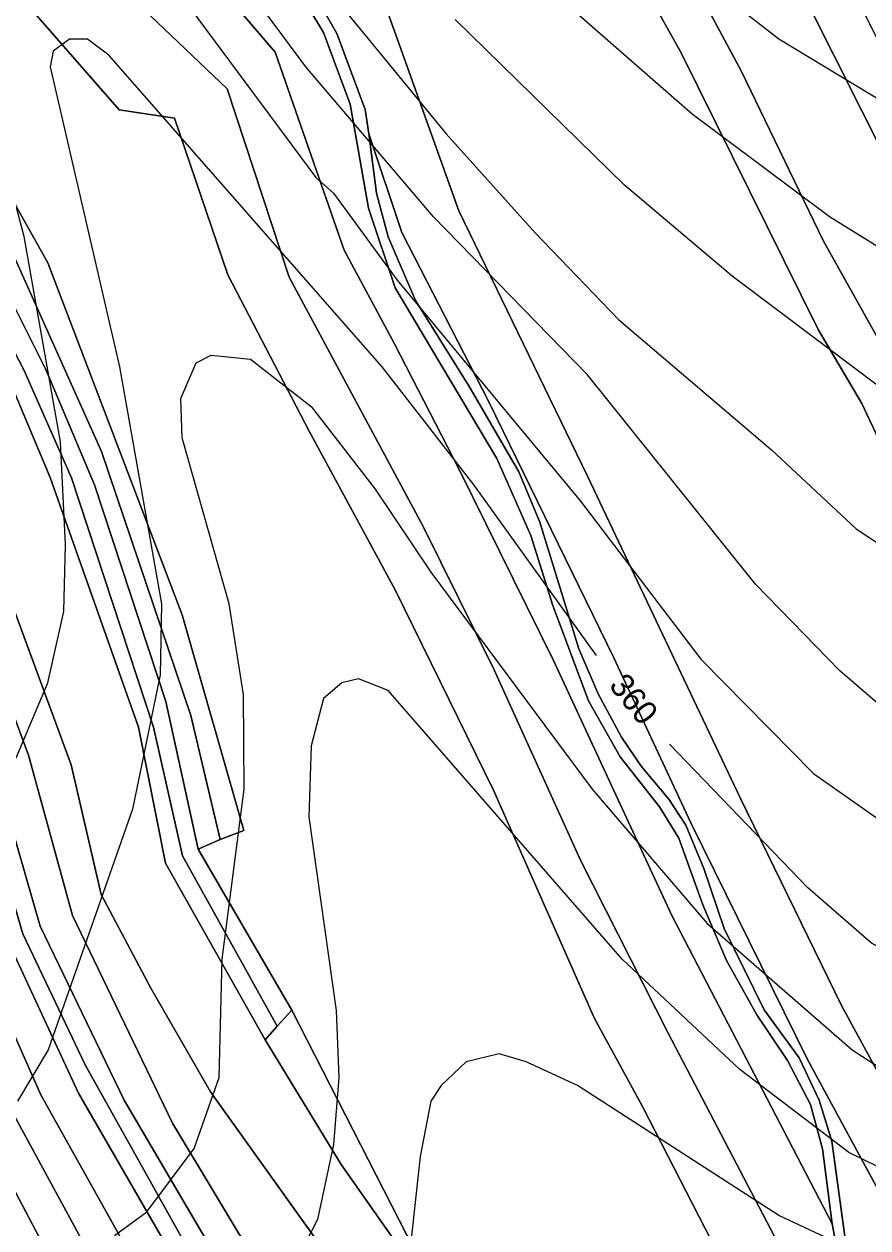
# Model space of a CAD drawing. Extents: x -510989 to -501240, y -1184665 to -1176089.
# Drawn here: x -503788.9 to -503575, y -1184005.1 to -1183700.2 of the extents above; entities that cross this region are included whole.
import ezdxf

# ---------------------------------------------------------------- set-up
doc = ezdxf.new("R2010")
doc.units = 0
for name, color, linetype in [('lesni_pozemek', 7, 'Continuous'), ('ostatni_plocha_x_ostatni_komunikace', 7, 'Continuous'), ('STAV_zaplavove_uzemi', 7, 'Continuous'), ('vrstevnice_01', 7, 'Continuous'), ('vrstevnice_02', 7, 'Continuous'), ('vrstevnice_04', 7, 'Continuous')]:
    doc.layers.add(name, color=color, linetype=linetype)

msp = doc.modelspace()

# ---------------------------------------------------------------- linework, layer by layer
at = {"layer": 'lesni_pozemek'}
for points in [[(-503728.62, -1183471.74), (-503691.85, -1183518.28), (-503657.3, -1183563.82), (-503630.7, -1183603.31), (-503587.48, -1183674.13), (-503559.07, -1183730.95), (-503535.3, -1183775.28), (-503494.59, -1183857.89), (-503467.6, -1183908.87), (-503444.44, -1183950.57), (-503452.2, -1183962.13), (-503472.04, -1183928.43), (-503489.75, -1183894.93), (-503504.72, -1183863.49), (-503545.08, -1183781.53), (-503569.52, -1183736.09), (-503597.66, -1183680.08), (-503640.08, -1183608.41), (-503666.58, -1183570.25), (-503702.2, -1183523.58), (-503704.29, -1183514.52), (-503710.83, -1183503.88), (-503732.92, -1183473.63), (-503757.64, -1183437.65)], [(-503702.34, -1183529.64), (-503702.2, -1183523.58), (-503666.58, -1183570.25), (-503640.08, -1183608.41), (-503597.66, -1183680.08), (-503569.52, -1183736.09), (-503545.08, -1183781.53), (-503504.72, -1183863.49), (-503489.75, -1183894.93), (-503472.04, -1183928.43), (-503452.2, -1183962.13), (-503464.49, -1183989.9), (-503471.18, -1183974.63), (-503503.05, -1183923.12), (-503533.25, -1183859.97), (-503566.41, -1183790.65), (-503586.33, -1183754.98), (-503607.08, -1183711.98), (-503630.64, -1183668.25), (-503652.21, -1183630.71), (-503678.37, -1183593.17), (-503718.7, -1183539.6), (-503708.68, -1183537.99), (-503704.44, -1183534.65)], [(-503723.14, -1183541.1), (-503718.7, -1183539.6), (-503678.37, -1183593.17), (-503652.21, -1183630.71), (-503630.64, -1183668.25), (-503607.08, -1183711.98), (-503586.33, -1183754.98), (-503566.41, -1183790.65), (-503533.25, -1183859.97), (-503503.05, -1183923.12), (-503471.18, -1183974.63), (-503464.49, -1183989.9), (-503470.2, -1184003.02), (-503478.74, -1183984.9), (-503487.73, -1183968.99), (-503513.65, -1183929.65), (-503543.5, -1183866.33), (-503576.52, -1183796.27), (-503587.58, -1183777.55), (-503622.31, -1183707.4), (-503662.92, -1183634.99), (-503689.76, -1183596.42), (-503727.89, -1183546.54)], [(-503973.7, -1183580.21), (-503967.42, -1183575.47), (-503953.32, -1183592.85), (-503940.15, -1183610.84), (-503925.17, -1183637.07), (-503875, -1183734.39), (-503853.34, -1183771.91), (-503838.27, -1183795.1), (-503823.83, -1183814.7), (-503794.54, -1183894.91), (-503784.87, -1183928.69), (-503763.52, -1183972.72), (-503707.12, -1184068.85), (-503713.72, -1184066.97), (-503735.95, -1184030.77), (-503773.46, -1183963.81), (-503789.2, -1183930.62), (-503800.23, -1183893.46), (-503821.51, -1183835.13), (-503830.08, -1183814.58), (-503857.78, -1183773.87), (-503877.64, -1183741.34), (-503929.28, -1183640.96)], [(-503923.76, -1183607.91), (-503941.52, -1183574.63), (-503907.86, -1183618.07), (-503877.34, -1183671.41), (-503857.25, -1183720.73), (-503808.09, -1183803.62), (-503776.93, -1183887.81), (-503769.34, -1183920.65), (-503756.77, -1183944.36), (-503741.61, -1183970.6), (-503712.6, -1184011.28), (-503680.96, -1184060.99), (-503667.47, -1184079.1), (-503694.94, -1184072.32), (-503751.3, -1183978.62), (-503776.6, -1183926), (-503787.83, -1183885.37), (-503816.55, -1183807.93), (-503850.68, -1183754.94), (-503867.66, -1183724.35), (-503888.17, -1183679.49), (-503918.27, -1183624.04), (-503926.42, -1183608.7)], [(-503932.58, -1183610.17), (-503926.42, -1183608.7), (-503918.27, -1183624.04), (-503888.17, -1183679.49), (-503867.66, -1183724.35), (-503850.68, -1183754.94), (-503816.55, -1183807.93), (-503787.83, -1183885.37), (-503776.6, -1183926), (-503751.3, -1183978.62), (-503694.94, -1184072.32), (-503707.12, -1184068.85), (-503763.52, -1183972.72), (-503784.87, -1183928.69), (-503794.54, -1183894.91), (-503823.83, -1183814.7), (-503838.27, -1183795.1), (-503853.34, -1183771.91), (-503875, -1183734.39), (-503925.17, -1183637.07), (-503940.15, -1183610.84)], [(-503900.05, -1183728.04), (-503892.22, -1183725.13), (-503880.05, -1183748.32), (-503866.2, -1183771.19), (-503833.89, -1183817.35), (-503804.04, -1183897.35), (-503791.87, -1183934.91), (-503775.13, -1183970.96), (-503720.64, -1184065.31), (-503730.86, -1184063.76), (-503751.05, -1184031.5), (-503784.63, -1183971.4), (-503801.21, -1183934.2), (-503812.45, -1183899.3), (-503831.14, -1183853.16), (-503842.23, -1183821.92), (-503877.86, -1183773.44), (-503893.19, -1183746.72), (-503904.72, -1183729.79)], [(-503904.72, -1183729.79), (-503893.19, -1183746.72), (-503877.86, -1183773.44), (-503842.23, -1183821.92), (-503831.14, -1183853.16), (-503812.45, -1183899.3), (-503801.21, -1183934.2), (-503784.63, -1183971.4), (-503751.05, -1184031.5), (-503730.86, -1184063.76), (-503741.77, -1184062.1), (-503759.53, -1184035.2), (-503797.58, -1183965.4), (-503808.59, -1183940.4), (-503820.43, -1183905.78), (-503841.38, -1183855.53), (-503850.64, -1183826.99), (-503885.26, -1183783.71), (-503890.42, -1183769.29), (-503901.81, -1183755.02), (-503908.95, -1183736.5)], [(-503889.81, -1183794.49), (-503885.26, -1183783.71), (-503850.64, -1183826.99), (-503841.38, -1183855.53), (-503820.43, -1183905.78), (-503808.59, -1183940.4), (-503797.58, -1183965.4), (-503759.53, -1184035.2), (-503741.77, -1184062.1), (-503754.12, -1184060.23), (-503768.09, -1184039.72), (-503805.46, -1183968.92), (-503816.03, -1183944.5), (-503829.24, -1183908.06), (-503850.19, -1183858.72), (-503859.75, -1183830.63)], [(-503895.32, -1183800.87), (-503889.81, -1183794.49), (-503859.75, -1183830.63), (-503850.19, -1183858.72), (-503829.24, -1183908.06), (-503816.03, -1183944.5), (-503805.46, -1183968.92), (-503768.09, -1184039.72), (-503754.12, -1184060.23), (-503767.28, -1184058.24), (-503778.46, -1184038.52), (-503810.59, -1183978.68), (-503824.96, -1183943.91), (-503860.61, -1183859.76), (-503868.2, -1183834.35)], [(-503724.76, -1183954.02), (-503721.05, -1183949.98), (-503691.91, -1184006.91), (-503654.54, -1184059.93), (-503635.2, -1184080.62), (-503637.88, -1184082.63), (-503657.74, -1184061.34), (-503708.48, -1183989.05), (-503727.82, -1183957.43)]]:
    msp.add_lwpolyline(points, close=True, dxfattribs=at)
for points in [[(-503662.92, -1183634.99), (-503622.31, -1183707.4), (-503587.58, -1183777.55), (-503576.52, -1183796.27), (-503543.5, -1183866.33), (-503513.65, -1183929.65), (-503487.73, -1183968.99), (-503478.74, -1183984.9), (-503470.2, -1184003.02), (-503477.05, -1184015.77), (-503492.95, -1184041.99), (-503503.44, -1184052.15), (-503519.21, -1184065.24), (-503532.36, -1184039.22), (-503581.63, -1183948.77), (-503607.29, -1183896.32), (-503646.1, -1183814.64), (-503678.66, -1183747.47), (-503699.47, -1183689.36)], [(-503929.28, -1183640.96), (-503877.64, -1183741.34), (-503857.78, -1183773.87), (-503830.08, -1183814.58), (-503821.51, -1183835.13), (-503800.23, -1183893.46), (-503789.2, -1183930.62), (-503773.46, -1183963.81), (-503735.95, -1184030.77), (-503713.72, -1184066.97), (-503718.36, -1184065.65), (-503720.64, -1184065.31), (-503775.13, -1183970.96), (-503791.87, -1183934.91), (-503804.04, -1183897.35), (-503833.89, -1183817.35), (-503866.2, -1183771.19), (-503880.05, -1183748.32), (-503892.22, -1183725.13), (-503903.02, -1183704.47), (-503915.09, -1183676.77)], [(-503846.64, -1183645.9), (-503830.48, -1183701.14), (-503808.25, -1183738.14), (-503783.4, -1183787.65), (-503771.07, -1183816.84), (-503753, -1183871.73), (-503744.79, -1183909.13), (-503721.05, -1183949.98), (-503724.76, -1183954.02), (-503748.71, -1183910.82), (-503756.11, -1183878.29), (-503776.89, -1183815.13), (-503788.99, -1183787.77), (-503810.24, -1183746.79), (-503834.07, -1183708.75), (-503851.8, -1183649.23)], [(-503824.66, -1183699.4), (-503800.08, -1183740), (-503769.25, -1183808.46), (-503746.65, -1183875.28), (-503739.21, -1183906.7), (-503744.79, -1183909.13), (-503753, -1183871.73), (-503771.07, -1183816.84), (-503783.4, -1183787.65), (-503808.25, -1183738.14), (-503830.48, -1183701.14), (-503846.64, -1183645.9)], [(-503851.8, -1183649.23), (-503834.07, -1183708.75), (-503810.24, -1183746.79), (-503788.99, -1183787.77), (-503776.89, -1183815.13), (-503756.11, -1183878.29), (-503748.71, -1183910.82), (-503724.76, -1183954.02), (-503727.82, -1183957.43), (-503753.06, -1183912.7), (-503759.87, -1183878.29), (-503782.29, -1183815.01), (-503791.33, -1183793.52), (-503809.77, -1183760.41), (-503823.51, -1183736.34), (-503839.1, -1183710.79), (-503858.14, -1183652.63)], [(-503858.14, -1183652.63), (-503839.1, -1183710.79), (-503823.51, -1183736.34), (-503809.77, -1183760.41), (-503791.33, -1183793.52), (-503782.29, -1183815.01), (-503759.87, -1183878.29), (-503753.06, -1183912.7), (-503727.82, -1183957.43), (-503708.48, -1183989.05), (-503657.74, -1184061.34), (-503637.88, -1184082.63), (-503639.64, -1184083.95), (-503644.69, -1184084.68), (-503667.47, -1184079.1), (-503680.96, -1184060.99), (-503712.6, -1184011.28), (-503741.61, -1183970.6), (-503756.77, -1183944.36), (-503769.34, -1183920.65), (-503776.93, -1183887.81), (-503808.09, -1183803.62), (-503857.25, -1183720.73), (-503877.34, -1183671.41)], [(-503699.47, -1183689.36), (-503678.66, -1183747.47), (-503646.1, -1183814.64), (-503607.29, -1183896.32), (-503581.63, -1183948.77), (-503532.36, -1184039.22), (-503519.21, -1184065.24), (-503531.57, -1184073.22), (-503552.36, -1184032.36), (-503590.26, -1183962.48), (-503619.87, -1183902.47), (-503639.35, -1183860.67), (-503671.07, -1183795.86), (-503693.13, -1183752.97), (-503701.5, -1183727.98), (-503702.43, -1183721.81), (-503709.64, -1183702.51), (-503720.81, -1183682.97)], [(-503770.96, -1183684.53), (-503737.4, -1183716.6), (-503721.68, -1183764.28), (-503687.75, -1183827.43), (-503669.79, -1183863.59), (-503647.74, -1183912.1), (-503625.59, -1183955.76), (-503578.51, -1184045.73), (-503590.64, -1184055.04), (-503632.12, -1183974.33), (-503644.33, -1183952.06), (-503669.88, -1183894.19), (-503694.71, -1183843.63), (-503716.62, -1183803.28), (-503737.24, -1183763.67), (-503750.79, -1183723.99), (-503764.78, -1183721.86), (-503787.11, -1183696.42)], [(-503744.59, -1183684.65), (-503725.26, -1183707.27), (-503707.77, -1183757.47), (-503695.01, -1183781.13), (-503678.56, -1183813.02), (-503654.69, -1183861.36), (-503624.66, -1183925.96), (-503584.07, -1184004.05), (-503579.34, -1184029.04), (-503578.51, -1184045.73), (-503625.59, -1183955.76), (-503647.74, -1183912.1), (-503669.79, -1183863.59), (-503687.75, -1183827.43), (-503721.68, -1183764.28), (-503737.4, -1183716.6), (-503770.96, -1183684.53)], [(-503718.95, -1183692.39), (-503713.01, -1183702.28), (-503706.27, -1183720.42), (-503701.62, -1183746.82), (-503694.87, -1183766.93), (-503669.06, -1183810.19), (-503660.45, -1183829.73), (-503654.87, -1183847.4), (-503645.8, -1183871.59), (-503637.78, -1183885.78), (-503627.78, -1183898.46), (-503622.89, -1183906.36), (-503616.86, -1183923.28), (-503610.8, -1183937.39), (-503603.17, -1183951.17), (-503595.36, -1183962.71), (-503589.55, -1183973.83), (-503586.48, -1183985.04), (-503584.07, -1184004.05), (-503624.66, -1183925.96), (-503654.69, -1183861.36), (-503678.56, -1183813.02), (-503695.01, -1183781.13), (-503707.77, -1183757.47), (-503725.26, -1183707.27), (-503744.59, -1183684.65)], [(-503819.92, -1183697.23), (-503794.33, -1183740.3), (-503782.85, -1183760.63), (-503748.83, -1183849.84), (-503733.2, -1183904.47), (-503739.21, -1183906.7), (-503746.65, -1183875.28), (-503769.25, -1183808.46), (-503800.08, -1183740), (-503824.66, -1183699.4)], [(-503787.11, -1183696.42), (-503764.78, -1183721.86), (-503750.79, -1183723.99), (-503737.24, -1183763.67), (-503716.62, -1183803.28), (-503694.71, -1183843.63), (-503669.88, -1183894.19), (-503644.33, -1183952.06), (-503632.12, -1183974.33), (-503590.64, -1184055.04)], [(-503580.18, -1184012.21), (-503584.13, -1183983.14), (-503587.3, -1183972.77), (-503592.44, -1183962.03), (-503601.25, -1183949.9), (-503611.41, -1183929.26), (-503616.57, -1183914.09), (-503621.15, -1183903.11), (-503625.45, -1183896.48), (-503632.43, -1183888.11), (-503637.43, -1183880.78), (-503643.36, -1183869.85), (-503648.24, -1183858.45), (-503658.13, -1183826.36), (-503663.48, -1183813.56), (-503676.15, -1183791.82), (-503689.64, -1183770.19), (-503696.62, -1183754.03), (-503699.53, -1183742.98), (-503701.5, -1183727.98), (-503693.13, -1183752.97), (-503671.07, -1183795.86), (-503639.35, -1183860.67), (-503619.87, -1183902.47), (-503590.26, -1183962.48), (-503552.36, -1184032.36)], [(-503691.91, -1184006.91), (-503721.05, -1183949.98), (-503744.79, -1183909.13), (-503739.21, -1183906.7), (-503733.2, -1183904.47), (-503748.83, -1183849.84), (-503782.85, -1183760.63), (-503794.33, -1183740.3)]]:
    msp.add_lwpolyline(points, dxfattribs=at)
at = {"layer": 'ostatni_plocha_x_ostatni_komunikace'}
for points in [[(-503720.81, -1183682.97), (-503709.64, -1183702.51), (-503702.43, -1183721.81), (-503701.5, -1183727.98), (-503699.53, -1183742.98), (-503696.62, -1183754.03), (-503689.64, -1183770.19), (-503676.15, -1183791.82), (-503663.48, -1183813.56), (-503658.13, -1183826.36), (-503648.24, -1183858.45), (-503643.36, -1183869.85), (-503637.43, -1183880.78), (-503632.43, -1183888.11), (-503625.45, -1183896.48), (-503621.15, -1183903.11), (-503616.57, -1183914.09), (-503611.41, -1183929.26), (-503601.25, -1183949.9), (-503592.44, -1183962.03), (-503587.3, -1183972.77), (-503584.13, -1183983.14), (-503580.18, -1184012.21)], [(-503579.34, -1184029.04), (-503584.07, -1184004.05), (-503586.48, -1183985.04), (-503589.55, -1183973.83), (-503595.36, -1183962.71), (-503603.17, -1183951.17), (-503610.8, -1183937.39), (-503616.86, -1183923.28), (-503622.89, -1183906.36), (-503627.78, -1183898.46), (-503637.78, -1183885.78), (-503645.8, -1183871.59), (-503654.87, -1183847.4), (-503660.45, -1183829.73), (-503669.06, -1183810.19), (-503694.87, -1183766.93), (-503701.62, -1183746.82), (-503706.27, -1183720.42), (-503713.01, -1183702.28), (-503718.95, -1183692.39)]]:
    msp.add_lwpolyline(points, dxfattribs=at)
at = {"layer": 'STAV_zaplavove_uzemi'}
msp.add_spline([(-502250.32, -1184002.61), (-502355.07, -1183875.41), (-502442.37, -1183790.61), (-502477.29, -1183700.82), (-502532.16, -1183578.61), (-502567.08, -1183448.91), (-502626.05, -1183402.34), (-502705.41, -1183380.59), (-502814.2, -1183349.87), (-502882.03, -1183297.39), (-502931.95, -1183237.24), (-503042.02, -1183107.97), (-503139.64, -1183018.94), (-503222.14, -1182957.59), (-503308.56, -1182839.96), (-503316.24, -1182784.92), (-503330.32, -1182756.77), (-503348.24, -1182719.65), (-503334.16, -1182651.82), (-503323.92, -1182595.5), (-503313.68, -1182526.39), (-503294.1, -1182480.5), (-503251.86, -1182396.03), (-503229.34, -1182314.37), (-503216.1, -1182227.15), (-503242.43, -1182174.5), (-503271.86, -1182129.59), (-503287.34, -1182081.58), (-503343.88, -1182028.1), (-503361.79, -1182008.91), (-503396.35, -1181952.59), (-503442.43, -1181933.39), (-503497.46, -1181888.6), (-503525.62, -1181860.44), (-503528.18, -1181837.4), (-503548.66, -1181767.01), (-503558.9, -1181729.89), (-503576.82, -1181682.53), (-503578.1, -1181621.1), (-503567.86, -1181572.46), (-503552.5, -1181536.63), (-503538.04, -1181458.36), (-503518.33, -1181411.9), (-503509.88, -1181341.51), (-503497.21, -1181207.63), (-503499.77, -1181097.56), (-503498.02, -1181031.35), (-503510.82, -1180970.85), (-503549.22, -1180952.23), (-503571.32, -1180940.6), (-503605.07, -1180937.11), (-503651.61, -1180939.44), (-503671.39, -1180917.33), (-503679.53, -1180892.89), (-503713.27, -1180871.95), (-503727.24, -1180859.15), (-503734.22, -1180833.55), (-503728.4, -1180799.81), (-503741.2, -1180770.72), (-503722.82, -1180725.17), (-503721.54, -1180703.41), (-503731.78, -1180697.01), (-503767.61, -1180699.57), (-503790.65, -1180697.01), (-503817.53, -1180697.01), (-503861.04, -1180686.77), (-503889.2, -1180675.25), (-503900.72, -1180668.85), (-503953.2, -1180679.09), (-503997.99, -1180697.01), (-504063.27, -1180722.61), (-504109.34, -1180749.49), (-504142.62, -1180776.36), (-504177.18, -1180796.84), (-504211.73, -1180817.32), (-504414.98, -1180961.5), (-504472.7, -1180998.11), (-504544.51, -1181068.5), (-504600.82, -1181143.12), (-504621.94, -1181196.62), (-504641.65, -1181267.01), (-504660.25, -1181350.62), (-504634.7, -1181398.32), (-504617.66, -1181447.72), (-504600.62, -1181492.01), (-504587, -1181548.23), (-504592.11, -1181628.29), (-504569.96, -1181682.81), (-504568.26, -1181664.07), (-504554.63, -1181621.48), (-504547.82, -1181597.63)], degree=3, dxfattribs=at)
at = {"layer": 'vrstevnice_01'}
for points in [[(-503392.59, -1183695), (-503413.81, -1183710), (-503445, -1183726), (-503474.31, -1183738), (-503497.69, -1183743), (-503524.19, -1183742), (-503547.81, -1183734), (-503597.59, -1183704), (-503628.31, -1183680)], [(-503318.3, -1183681.98), (-503390.91, -1183753), (-503439.59, -1183798), (-503454.19, -1183808), (-503464.69, -1183812), (-503485.31, -1183817), (-503501.59, -1183818), (-503515.19, -1183816), (-503542.31, -1183808), (-503566.81, -1183796), (-503609.41, -1183764), (-503636.69, -1183741), (-503679.59, -1183699)], [(-503325.32, -1183759.01), (-503354.31, -1183783), (-503373.41, -1183800), (-503374.19, -1183803), (-503380.09, -1183809), (-503400, -1183849), (-503402.69, -1183857), (-503406.59, -1183863), (-503419.41, -1183874), (-503430.59, -1183880), (-503457.59, -1183889), (-503490.91, -1183895), (-503519, -1183895), (-503536, -1183893), (-503548.81, -1183889), (-503565.81, -1183878), (-503582.09, -1183864), (-503603.5, -1183842), (-503646.09, -1183789), (-503685.09, -1183749), (-503717.5, -1183711), (-503736, -1183686)], [(-503643.79, -1183860.07), (-503674.81, -1183817), (-503698.09, -1183787), (-503767.41, -1183708), (-503772.81, -1183704), (-503777.41, -1183704), (-503781.5, -1183707), (-503782.31, -1183711), (-503764.69, -1183787), (-503754.09, -1183847), (-503754.41, -1183865), (-503761.41, -1183899), (-503782.81, -1183960), (-503790.59, -1183973)], [(-503332.43, -1183837.02), (-503343.59, -1183846), (-503352.09, -1183859), (-503358, -1183884), (-503362.09, -1183896), (-503372.19, -1183909), (-503383.31, -1183916), (-503438.09, -1183937), (-503481.91, -1183950), (-503500.41, -1183954), (-503515.81, -1183955), (-503539.5, -1183951), (-503548.31, -1183947), (-503574.09, -1183933), (-503590.19, -1183919), (-503625.28, -1183882.53)], [(-503365.81, -1183956), (-503479.69, -1183990), (-503512.19, -1183998), (-503527.41, -1184001), (-503543.69, -1184000), (-503561.5, -1183995), (-503579.81, -1183986), (-503607.41, -1183965), (-503637.31, -1183937), (-503696.59, -1183869), (-503704.09, -1183866), (-503708.31, -1183867), (-503713, -1183871), (-503716.09, -1183883), (-503716.69, -1183901), (-503709.81, -1183950), (-503709.09, -1183967), (-503710.5, -1183984), (-503714.5, -1184003), (-503720.69, -1184015)]]:
    msp.add_lwpolyline(points, dxfattribs=at)
at = {"layer": 'vrstevnice_02'}
for points in [[(-503758.69, -1183680), (-503714.91, -1183739), (-503710.5, -1183743), (-503694.31, -1183765), (-503647.81, -1183821), (-503617.31, -1183861), (-503588.81, -1183890), (-503566, -1183906), (-503540, -1183922), (-503527.09, -1183927), (-503511.31, -1183930), (-503490.31, -1183927), (-503469.5, -1183923), (-503448.5, -1183917), (-503421.69, -1183908), (-503392.69, -1183893), (-503385.69, -1183886), (-503381, -1183870), (-503380.31, -1183862), (-503374.19, -1183846), (-503371.81, -1183841), (-503350.41, -1183814), (-503342.19, -1183806), (-503328.6, -1183795.01)], [(-503718, -1183684), (-503681.91, -1183728), (-503659.31, -1183753), (-503638.19, -1183775), (-503599.41, -1183808), (-503577.91, -1183828), (-503559.81, -1183840), (-503542, -1183848), (-503520, -1183855), (-503499.31, -1183858), (-503466.81, -1183853), (-503448.41, -1183848), (-503435.09, -1183842), (-503427.19, -1183836), (-503424, -1183832), (-503405.59, -1183800), (-503392.19, -1183786), (-503321.94, -1183721.94)], [(-503363, -1183696), (-503385.09, -1183718), (-503419.69, -1183746), (-503441.19, -1183760), (-503464.59, -1183770), (-503484.31, -1183776), (-503505.09, -1183779), (-503522.09, -1183779), (-503534.69, -1183777), (-503542.91, -1183774), (-503557.19, -1183766), (-503584.69, -1183749), (-503619.5, -1183723), (-503651.59, -1183695)], [(-503790.91, -1183886), (-503782.91, -1183867), (-503778.81, -1183849), (-503778.41, -1183832), (-503779.69, -1183806), (-503788.91, -1183754), (-503796.91, -1183724)], [(-503766, -1184007), (-503757.81, -1184001), (-503745.81, -1183985), (-503739.41, -1183967), (-503738.69, -1183937), (-503733.09, -1183894), (-503733.31, -1183870), (-503736.91, -1183847), (-503748.81, -1183805), (-503749.19, -1183795), (-503745.31, -1183786), (-503741.5, -1183784), (-503731.5, -1183785), (-503716.09, -1183797), (-503699.91, -1183818), (-503685.81, -1183839), (-503644.91, -1183894), (-503615.69, -1183928), (-503579, -1183960), (-503569.69, -1183966)], [(-503384.81, -1183982), (-503445.5, -1184000), (-503473.69, -1184010), (-503497.31, -1184016), (-503526.59, -1184019), (-503552.59, -1184018), (-503580.41, -1184010), (-503597.59, -1184002), (-503648.59, -1183969), (-503661.59, -1183963), (-503668.5, -1183961), (-503676.81, -1183963), (-503683.19, -1183969), (-503685.81, -1183973), (-503688.5, -1183987), (-503691.91, -1184018), (-503700.59, -1184033), (-503705.81, -1184039), (-503720.31, -1184048), (-503726.81, -1184050), (-503757.59, -1184054), (-503761.69, -1184063), (-503765.81, -1184064), (-503818.59, -1184065)]]:
    msp.add_lwpolyline(points, dxfattribs=at)

# ---------------------------------------------------------------- texts
at = {"layer": 'vrstevnice_04'}
msp.add_text('360', height=6, rotation=309.1188, dxfattribs=at).set_placement((-503640.85, -1183867.82))

doc.saveas('drawing.dxf')
